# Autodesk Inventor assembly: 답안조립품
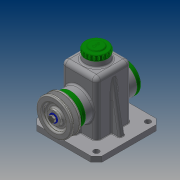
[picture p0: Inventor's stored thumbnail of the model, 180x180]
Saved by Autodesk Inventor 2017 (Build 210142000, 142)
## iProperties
Part Number: 답안조립품
Material: 일반
Document SubType Name: Assembly
Designer: 20
Author: 20
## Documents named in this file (14)
- C:\Users\20\Desktop\470818V1006\답안조립품.iam
- C:\Users\20\Desktop\470818V1006\본체.ipt
- C:\Users\20\Desktop\470818V1006\앞커버.ipt
- C:\Users\20\Desktop\470818V1006\뒤커버.ipt
- C:\Users\20\Desktop\470818V1006\축.ipt
- C:\Users\20\Desktop\470818V1006\베어링 15 x 35 x 11.ipt
- C:\Users\20\Desktop\470818V1006\오일실 15 25 7.ipt
- C:\Users\20\Desktop\470818V1006\V-벨트풀리.ipt
- C:\Users\20\Desktop\470818V1006\키 5 x 5 x 14.ipt
- C:\Users\20\Desktop\470818V1006\볼트 M4 x 10.ipt
- C:\Users\20\Desktop\470818V1006\멈춤링 15 x 1.ipt
- C:\Users\20\Desktop\470818V1006\와셔.ipt
- C:\Users\20\Desktop\470818V1006\볼트 M6 x 12.ipt
- C:\Users\20\Desktop\470818V1006\상부캡.ipt
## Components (1 placed, 1 different names)
1. V-벨트풀리:1 — 플러쉬:1
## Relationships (1: Flush 1)
- 플러쉬:1 [Flush]: V-벨트풀리:1
